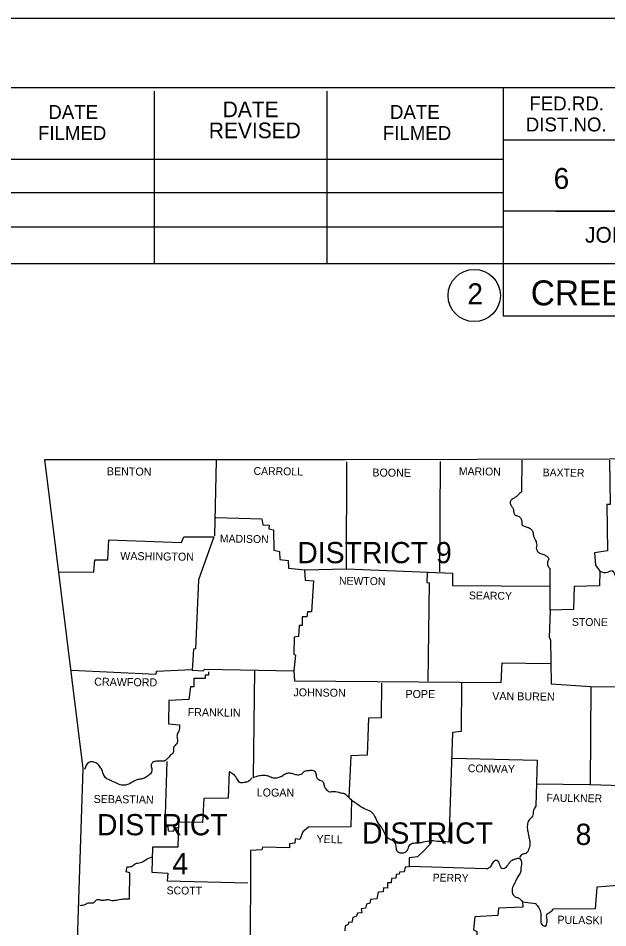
# Model space of a CAD drawing. Extents: x 1373094 to 1376427, y 1168361 to 1170494.
# Drawn here: x 1375677 to 1376007, y 1169984 to 1170494 of the extents above; entities that cross this region are included whole.
import ezdxf

# ---------------------------------------------------------------- set-up
doc = ezdxf.new("R2010")
doc.units = 0
for name, color, linetype in [('Default', 7, 'Continuous'), ('R_Border', 7, 'Continuous'), ('R_No Plot', 7, 'Continuous')]:
    doc.layers.add(name, color=color, linetype=linetype)

msp = doc.modelspace()

# ---------------------------------------------------------------- linework, layer by layer
at = {"layer": 'Default'}
for points in [[(1375691.37, 1170246.85), (1375860.2, 1170246.75), (1376008.36, 1170247.06), (1376183.15, 1170249.77), (1376264.17, 1170251.65)], [(1375691.37, 1170246.85), (1375712.98, 1170073.32), (1375703.58, 1169790.06)], [(1375787.74, 1170246.22), (1375786.8, 1170203.94)], [(1375959.18, 1170246.43), (1375958.98, 1170228.58)], [(1376008.36, 1170246.43), (1376008.57, 1170221.58), (1376006.8, 1170221.48), (1376007.11, 1170195.48), (1375999.8, 1170194.44), (1376000.43, 1170187.44), (1376002.93, 1170184.21), (1376002.72, 1170175.96), (1375988.52, 1170175.44), (1375988, 1170162.7), (1375975.05, 1170162.28), (1375974.43, 1170146.83), (1375975.16, 1170145.57), (1375975.47, 1170120.93), (1375997.82, 1170119.47), (1375997.5, 1170064.45), (1376015.25, 1170063.93), (1376015.25, 1170007.96), (1376001.26, 1170006.92), (1376000.22, 1169994.6), (1375976.73, 1169994.49)], [(1375787.53, 1170214.28), (1375813.22, 1170213.44), (1375813.84, 1170210.1), (1375817.39, 1170209.99), (1375817.29, 1170207.91), (1375819.79, 1170207.28), (1375820, 1170195.9), (1375823.24, 1170195.17), (1375823.45, 1170190.68), (1375828.04, 1170190.05), (1375828.25, 1170185.88), (1375837.34, 1170184.94), (1375860.72, 1170185.46), (1375860.93, 1170245.49)], [(1375913.24, 1170245.7), (1375912.93, 1170183.68)], [(1375699.62, 1170183.68), (1375719.14, 1170183.58), (1375719.66, 1170190.47), (1375726.87, 1170190.47), (1375727.49, 1170201.64), (1375768.21, 1170200.18), (1375769.47, 1170203.31), (1375786.28, 1170203.42), (1375777.82, 1170179.19), (1375776.15, 1170140.46), (1375774.9, 1170140.35), (1375774.27, 1170128.66), (1375780.43, 1170128.14), (1375781.37, 1170129.08), (1375831.18, 1170128.14), (1375831.7, 1170122.6)], [(1375837.13, 1170184.73), (1375837.54, 1170179.09), (1375842.35, 1170178.78), (1375841.09, 1170161.24), (1375838.9, 1170161.34), (1375838.48, 1170158.52), (1375835.98, 1170158.52), (1375835.87, 1170153.72), (1375834.31, 1170153.61), (1375833.79, 1170147.45), (1375831.49, 1170147.14), (1375831.18, 1170137.74), (1375832.22, 1170137.01), (1375831.18, 1170128.14)], [(1375860.72, 1170185.46), (1375920.24, 1170182.95), (1375920.13, 1170176.17), (1375974.74, 1170175.75)], [(1375975.05, 1170162.28), (1375974.95, 1170185.77)], [(1375905.93, 1170183.27), (1375905.83, 1170177.84), (1375907.19, 1170177.52), (1375906.35, 1170122.4)], [(1375706.51, 1170128.56), (1375754.01, 1170126.36), (1375754.22, 1170128.03), (1375774.06, 1170128.97)], [(1375809.25, 1170128.56), (1375808.52, 1170068.31)], [(1375831.7, 1170122.6), (1375947.59, 1170121.66), (1375948.12, 1170132.63), (1375975.05, 1170132.31)], [(1375783.46, 1170127.72), (1375783.46, 1170125.84), (1375781.48, 1170125.84), (1375781.58, 1170123.96), (1375775.21, 1170123.86), (1375775.11, 1170119.16), (1375773.33, 1170119.16), (1375772.39, 1170112.16), (1375761.11, 1170111.64), (1375761.01, 1170098.38), (1375767.07, 1170097.96)], [(1375880.38, 1170121.28), (1375880.28, 1170101.76), (1375873.07, 1170101.65), (1375872.45, 1170080.87), (1375863.26, 1170080.56), (1375862.12, 1170057.13)], [(1375925.35, 1170121.25), (1375925.15, 1170094.1), (1375920.13, 1170093.68), (1375918.15, 1170032.29)], [(1375997.82, 1170119.47), (1376051.48, 1170119.16), (1376056.08, 1170121.35), (1376055.77, 1170080.53), (1376052.63, 1170079.17), (1376049.81, 1170076.77), (1376048.87, 1170075.83), (1376048.77, 1170064.13), (1376015.25, 1170064.13)], [(1375919.93, 1170079.17), (1375967.64, 1170078.02), (1375967.02, 1170052.23)], [(1375759.97, 1170077.29), (1375758.92, 1170041.37), (1375760.49, 1170040.96), (1375760.8, 1170038.45), (1375763.93, 1170038.24), (1375764.25, 1170040.02), (1375766.75, 1170040.43)], [(1375795.05, 1170071.65), (1375794.32, 1170056.72), (1375780.74, 1170056.62), (1375780.01, 1170043.04), (1375766.54, 1170043.36), (1375766.13, 1170029.37), (1375752.03, 1170029.26), (1375751.61, 1170015.27), (1375760.49, 1170014.75), (1375760.18, 1170010.47), (1375805.49, 1170009.22)], [(1375967.12, 1170064.87), (1375997.5, 1170064.45)], [(1375863.65, 1170055.68), (1375863.23, 1170040.64), (1375839.42, 1170040.54), (1375836.29, 1170037.82), (1375834.52, 1170033.65), (1375831.91, 1170033.86), (1375831.8, 1170031.45), (1375828.77, 1170031.14), (1375828.88, 1170028.95), (1375813.74, 1170029.37), (1375813.22, 1170027.7), (1375806.95, 1170027.49), (1375806.74, 1169966.41)], [(1375908.44, 1170031.87), (1375904.68, 1170027.8), (1375900.61, 1170023.94), (1375895.91, 1170023.21), (1375895.91, 1170018.3), (1375893.61, 1170017.99), (1375893.2, 1170015.48), (1375890.59, 1170015.27), (1375890.38, 1170014.12), (1375888.6, 1170014.02), (1375888.5, 1170011.83), (1375885.99, 1170011.72), (1375885.78, 1170009.22), (1375883.69, 1170009.22), (1375883.8, 1170006.29), (1375881.5, 1170006.5), (1375881.4, 1170004.2), (1375878.58, 1170004), (1375877.74, 1170000.24), (1375874.19, 1169999.92), (1375873.88, 1169997.83), (1375872, 1169997.31), (1375871.48, 1169995.12), (1375869.08, 1169994.6), (1375869.29, 1169992.41), (1375866.88, 1169992.2), (1375866.47, 1169990.53), (1375864.27, 1169989.9), (1375863.75, 1169987.08), (1375862.08, 1169987.19), (1375861.56, 1169985.72), (1375859.99, 1169985.2), (1375859.89, 1169982.38)], [(1375738.98, 1170000.13), (1375739.29, 1170014.85), (1375737.2, 1170015.48), (1375737.83, 1170018.3)], [(1375939.03, 1170017.05), (1375896.02, 1170018.4)], [(1375966.91, 1169997.52), (1375959.39, 1169998.36), (1375959.71, 1169995.54), (1375946.03, 1169995.02), (1375945.61, 1169990.94), (1375932.77, 1169990.21), (1375932.04, 1169982.9), (1375933.92, 1169981.96), (1375933.92, 1169977.3)]]:
    msp.add_lwpolyline(points, dxfattribs=at)
for points in [[(1375958.98, 1170228.58), (1375957.1, 1170227.01), (1375955.43, 1170225.55), (1375952.92, 1170223.78), (1375952.61, 1170222.11), (1375953.44, 1170220.44), (1375954.28, 1170219.08), (1375954.59, 1170217.2), (1375955.32, 1170215.63), (1375957.1, 1170215.01), (1375958.56, 1170213.65), (1375959.08, 1170211.77), (1375959.29, 1170209.99), (1375960.96, 1170209.16), (1375962.84, 1170208.53), (1375964.61, 1170207.28), (1375965.45, 1170205.71), (1375965.66, 1170203.73), (1375966.39, 1170202.16), (1375967.22, 1170200.28), (1375967.43, 1170198.72), (1375967.22, 1170197.15), (1375967.64, 1170195.69), (1375969, 1170194.23), (1375971.4, 1170193.5), (1375973.07, 1170192.45), (1375974.22, 1170190.99), (1375973.49, 1170189.22), (1375973.59, 1170187.65), (1375974.53, 1170185.77)], [(1376002.93, 1170184.21), (1376007.11, 1170183.47), (1376009.62, 1170184.41), (1376011.39, 1170181.7), (1376012.33, 1170179.61), (1376013.9, 1170176.58), (1376016.4, 1170175.64), (1376018.28, 1170173.97), (1376018.28, 1170172.2), (1376016.61, 1170170.53), (1376015.36, 1170168.86), (1376015.78, 1170166.87), (1376016.19, 1170164.16), (1376016.19, 1170161.55), (1376015.57, 1170159.15), (1376015.04, 1170156.95), (1376015.57, 1170155.08), (1376017.55, 1170155.39), (1376019.64, 1170156.95), (1376021.83, 1170156.95), (1376023.92, 1170155.81), (1376026.11, 1170153.82), (1376028.3, 1170154.24), (1376030.08, 1170154.76), (1376032.59, 1170155.49), (1376034.36, 1170154.55), (1376035.93, 1170153.3), (1376037.81, 1170151.32), (1376039.58, 1170150.06), (1376041.88, 1170148.92), (1376044.7, 1170148.18), (1376047.31, 1170146.41), (1376047.73, 1170143.38), (1376047.62, 1170140.77), (1376047.41, 1170137.53), (1376047.2, 1170133.98), (1376047.52, 1170130.54), (1376048.67, 1170128.24), (1376050.13, 1170125.53), (1376050.54, 1170123.02), (1376050.44, 1170119.05)], [(1375767.07, 1170097.96), (1375767.07, 1170095.77), (1375766.23, 1170093.47), (1375765.71, 1170091.49), (1375766.02, 1170088.88), (1375765.08, 1170086.79), (1375763.73, 1170085.12), (1375763.73, 1170083.03), (1375762.16, 1170080.84), (1375760.49, 1170079.17), (1375759.03, 1170077.81), (1375756.42, 1170077.6), (1375754.22, 1170077.5), (1375752.03, 1170076.77), (1375751.2, 1170075.2), (1375751.61, 1170072.8), (1375750.78, 1170070.5), (1375748.59, 1170068.73), (1375746.18, 1170067.58), (1375743.68, 1170067.16), (1375740.23, 1170065.49), (1375737.1, 1170064.13), (1375733.76, 1170064.34), (1375730.63, 1170065.7), (1375727.81, 1170066.95), (1375725.61, 1170068.21), (1375723.84, 1170072.07), (1375722.69, 1170074.16), (1375720.71, 1170076.25), (1375718.31, 1170077.08), (1375716.32, 1170076.87), (1375713.92, 1170072.8)], [(1375808.52, 1170068.31), (1375811.96, 1170069.46), (1375814.47, 1170069.67), (1375816.98, 1170069.25), (1375819.59, 1170068.21), (1375822.4, 1170068.42), (1375824.49, 1170069.15), (1375826.58, 1170070.5), (1375828.88, 1170070.92), (1375831.07, 1170070.5), (1375833.37, 1170069.88), (1375835.87, 1170070.61), (1375837.34, 1170071.97), (1375839.84, 1170072.38), (1375842.03, 1170072.38), (1375843.6, 1170070.61), (1375843.91, 1170068.73), (1375845.9, 1170066.95), (1375847.67, 1170065.81), (1375848.19, 1170063.61), (1375849.13, 1170062.05), (1375850.07, 1170061), (1375851.43, 1170060.38), (1375853.73, 1170060.58), (1375857.28, 1170059.85), (1375859.58, 1170059.33), (1375861.66, 1170057.56), (1375863.65, 1170055.68)], [(1375795.05, 1170071.65), (1375797.35, 1170070.19), (1375799.12, 1170067.79), (1375800.69, 1170065.81), (1375803.3, 1170065.7), (1375805.39, 1170066.12), (1375807.79, 1170068.21)], [(1375863.65, 1170055.68), (1375867.3, 1170053.17), (1375870.75, 1170050.98), (1375874.3, 1170049.41), (1375876.28, 1170047.12), (1375878.06, 1170043.57), (1375879.52, 1170041.37), (1375881.4, 1170038.66), (1375882.75, 1170035.63), (1375884.95, 1170033.96), (1375887.24, 1170032.5), (1375888.39, 1170029.89), (1375888.92, 1170027.28), (1375891.42, 1170026.03), (1375893.82, 1170026.55), (1375895.18, 1170028.11), (1375896.43, 1170030.83), (1375899.25, 1170031.66), (1375902.91, 1170031.98), (1375907.08, 1170032.92), (1375911.68, 1170032.71), (1375918.15, 1170032.29)], [(1375967.02, 1170052.23), (1375965.66, 1170049.83), (1375965.03, 1170046.7), (1375963.36, 1170044.71), (1375962.32, 1170042.42), (1375962.21, 1170039.39), (1375962.73, 1170036.68), (1375963.26, 1170034.06), (1375963.67, 1170031.66), (1375963.15, 1170028.64), (1375961.79, 1170026.03), (1375959.71, 1170025.29), (1375957.72, 1170023.52)], [(1375737.83, 1170018.3), (1375740.13, 1170018.51), (1375742.32, 1170019.97), (1375745.24, 1170020.6), (1375748.17, 1170022.16), (1375751.82, 1170023.83)], [(1375939.03, 1170017.05), (1375941.64, 1170018.51), (1375943, 1170020.7), (1375944.67, 1170022.06), (1375946.34, 1170020.18), (1375947.8, 1170017.46), (1375949.37, 1170017.46), (1375951.35, 1170019.34), (1375952.61, 1170021.01), (1375954.17, 1170022.27), (1375955.84, 1170022.79), (1375957.62, 1170023), (1375958.98, 1170021.01), (1375958.56, 1170017.88), (1375958.56, 1170015.79), (1375957.41, 1170013.6), (1375956.16, 1170011.3), (1375954.8, 1170008.69), (1375953.75, 1170005.87), (1375953.96, 1170003.16), (1375955.43, 1170001.38), (1375957.1, 1170000.86), (1375959.39, 1169998.57)], [(1375738.98, 1170000.13), (1375735.95, 1170000.03), (1375732.51, 1169999.61), (1375729.37, 1169999.19), (1375726.55, 1169999.71), (1375723.94, 1169999.3), (1375722.17, 1169999.71), (1375719.98, 1169999.19), (1375718.72, 1169997.94), (1375716.11, 1169997.94), (1375714.23, 1169997.1), (1375711.21, 1169996.37)], [(1375966.91, 1169997.52), (1375968.69, 1169995.22), (1375969.73, 1169992.09), (1375969.73, 1169988.54), (1375970.57, 1169985.62), (1375972.24, 1169984.99), (1375973.28, 1169987.5), (1375973.07, 1169990), (1375973.07, 1169991.47), (1375974.85, 1169992.72), (1375976.73, 1169994.49)]]:
    msp.add_spline(points, degree=3, dxfattribs=at)
at = {"layer": 'R_Border'}
for p, q in [((1373217.75, 1170455.42), (1376379.55, 1170455.42)), ((1375948.55, 1170455.42), (1375948.55, 1170327.42)), ((1375753.15, 1170356.62), (1375753.15, 1170453.42)), ((1375849.95, 1170356.62), (1375849.95, 1170453.42)), ((1376379.55, 1170426.02), (1375948.55, 1170426.02)), ((1375556.95, 1170415.22), (1375948.55, 1170415.22)), ((1375556.95, 1170396.62), (1375948.55, 1170396.62)), ((1376379.55, 1170386.02), (1375948.55, 1170386.02)), ((1375978.15, 1170386.02), (1376379.55, 1170386.02)), ((1375556.95, 1170377.22), (1375948.55, 1170377.22)), ((1376379.55, 1170356.62), (1375556.95, 1170356.62)), ((1375948.55, 1170327.42), (1376379.55, 1170327.42))]:
    msp.add_line(p, q, dxfattribs=at)
msp.add_circle((1375932.41, 1170338.78), 14.67, dxfattribs=at)
at = {"layer": 'R_No Plot'}
msp.add_line((1373093.74, 1170494.36), (1376427.07, 1170494.36), dxfattribs=at)
msp.add_lwpolyline([(1373093.67, 1170494.36), (1376427.07, 1170494.36), (1376427.07, 1168360.99), (1373093.67, 1168360.99)], close=True, dxfattribs=at)

# ---------------------------------------------------------------- texts
at = {"layer": 'Default'}
for s, height, rotation, p in [('BENTON', 4.49, 359.2527, (1375726.35, 1170237.98)), ('CARROLL', 4.386, 359.1481, (1375808.62, 1170238.19)), ('BOONE', 4.49, 359.4001, (1375875.24, 1170237.25)), ('MARION', 4.386, 359.1854, (1375923.79, 1170238.08)), ('BAXTER', 4.386, 359.256, (1375970.77, 1170237.35)), ('MADISON', 4.386, 359.0906, (1375789.72, 1170200.28)), ('WASHINGTON', 4.489, 359.232, (1375733.86, 1170190.47)), ('NEWTON', 4.386, 359.2717, (1375856.55, 1170176.58)), ('SEARCY', 4.384, 359.2527, (1375929.43, 1170168.34)), ('STONE', 4.384, 359.4001, (1375987.17, 1170153.51)), ('CRAWFORD', 4.489, 359.2771, (1375719.25, 1170119.89)), ('JOHNSON', 4.49, 359.3514, (1375830.97, 1170113.94)), ('POPE', 4.49, 359.6155, (1375893.82, 1170113)), ('VAN BUREN', 4.49, 359.3508, (1375942.48, 1170111.85)), ('FRANKLIN', 4.49, 359.1816, (1375771.66, 1170102.87)), ('CONWAY', 4.384, 359.0372, (1375928.8, 1170071.34)), ('LOGAN', 4.49, 359.3969, (1375810.4, 1170057.77)), ('SEBASTIAN', 4.489, 359.2816, (1375718.93, 1170054.11)), ('FAULKNER', 4.386, 359.2486, (1375972.86, 1170054.84)), ('YELL', 4.49, 359.1987, (1375843.91, 1170031.66)), ('PERRY', 4.386, 359.0858, (1375909.07, 1170010.05)), ('SCOTT', 4.386, 359.4063, (1375759.86, 1170002.85)), ('PULASKI', 4.49, 359.0531, (1375979.02, 1169986.35))]:
    msp.add_text(s, height=height, rotation=rotation, dxfattribs=at).set_placement(p)
for s, height, p in [('DISTRICT 9', 11.903, (1375833.16, 1170188.59)), ('DISTRICT', 11.903, (1375720.81, 1170035.94)), ('DISTRICT', 11.903, (1375869.49, 1170031.25)), ('8', 11.9, (1375989.25, 1170030.52)), ('4', 11.9, (1375763.1, 1170014.02))]:
    msp.add_text(s, height=height, dxfattribs=at).set_placement(p)
at = {"layer": 'R_Border'}
for s, height, p in [('FED.RD.', 7.819, (1375963.35, 1170442.62)), ('DATE', 7.819, (1375693.55, 1170437.82)), ('DATE', 8.792, (1375791.35, 1170438.82)), ('DATE', 7.819, (1375885.15, 1170437.82)), ('REVISED', 8.792, (1375783.55, 1170427.02)), ('DIST.NO.', 7.819, (1375961.35, 1170430.82)), ('FILMED', 7.819, (1375687.75, 1170426.02)), ('FILMED', 7.819, (1375881.15, 1170426.02)), ('6', 11.72, (1375976.95, 1170398.62)), ('JOB NO.', 8.792, (1375994.55, 1170368.42)), ('CREEK AT L.M. 6.07 STR. & APPRS. (S)', 14, (1375964.12, 1170333.25)), ('2', 11.72, (1375928.59, 1170333.91))]:
    msp.add_text(s, height=height, dxfattribs=at).set_placement(p)

doc.saveas('drawing.dxf')
